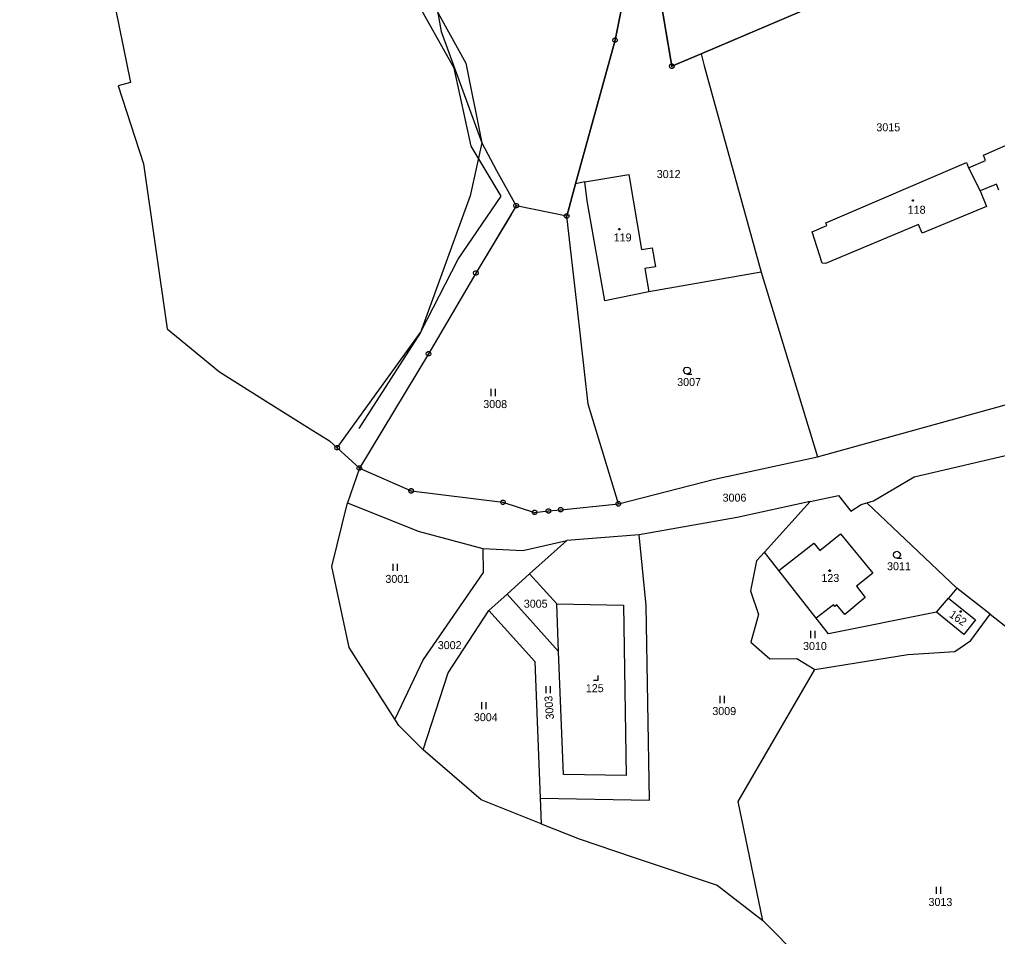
# Model space of a CAD drawing. Extents: x -580551 to -575069, y -1073031 to -1067931.
# Drawn here: x -578557.5 to -578349.8, y -1072489.2 to -1072294.4 of the extents above; entities that cross this region are included whole.
import ezdxf

# ---------------------------------------------------------------- set-up
doc = ezdxf.new("R2010")
doc.units = 0
for name, color, linetype in [('Druh pozemku', 7, 'Continuous'), ('Geodetické body', 7, 'Continuous'), ('Hranice krajů', 7, 'Continuous'), ('Hranice okresů', 7, 'Continuous'), ('Hranice z rastru', 7, 'Continuous'), ('Katastrální hranice', 7, 'Continuous'), ('Parcela', 7, 'Continuous'), ('Parcelní číslo', 7, 'Continuous'), ('Parcelní číslo_stavba', 7, 'Continuous')]:
    doc.layers.add(name, color=color, linetype=linetype)

msp = doc.modelspace()

# ---------------------------------------------------------------- linework, layer by layer
at = {"layer": 'Druh pozemku'}
for p, q in [((-578457.42, -1072372.9), (-578457.42, -1072374.4)), ((-578456.42, -1072374.4), (-578456.42, -1072372.9)), ((-578478.21, -1072410.03), (-578478.21, -1072411.53)), ((-578477.21, -1072411.53), (-578477.21, -1072410.03)), ((-578389.51, -1072424.29), (-578389.51, -1072425.79)), ((-578388.51, -1072425.79), (-578388.51, -1072424.29)), ((-578445.73, -1072435.98), (-578445.73, -1072437.48)), ((-578444.73, -1072437.48), (-578444.73, -1072435.98)), ((-578459.43, -1072439.4), (-578459.43, -1072440.9)), ((-578458.43, -1072440.9), (-578458.43, -1072439.4)), ((-578408.78, -1072438.1), (-578408.78, -1072439.6)), ((-578407.78, -1072439.6), (-578407.78, -1072438.1)), ((-578362.86, -1072478.65), (-578362.86, -1072480.15)), ((-578361.86, -1072480.15), (-578361.86, -1072478.65))]:
    msp.add_line(p, q, dxfattribs=at)
for points in [[(-578367.69, -1072332.7), (-578367.6, -1072332.85), (-578367.69, -1072333), (-578367.87, -1072333), (-578367.96, -1072332.85), (-578367.87, -1072332.7)], [(-578430.04, -1072338.8), (-578429.95, -1072338.95), (-578430.04, -1072339.1), (-578430.22, -1072339.1), (-578430.31, -1072338.95), (-578430.22, -1072338.8)], [(-578385.38, -1072411.34), (-578385.29, -1072411.49), (-578385.38, -1072411.64), (-578385.56, -1072411.64), (-578385.65, -1072411.49), (-578385.56, -1072411.34)], [(-578357.53, -1072420), (-578357.44, -1072420.15), (-578357.53, -1072420.3), (-578357.71, -1072420.3), (-578357.8, -1072420.15), (-578357.71, -1072420)]]:
    msp.add_lwpolyline(points, close=True, dxfattribs=at)
for points in [[(-578415.74, -1072369.72), (-578416.12, -1072369.62), (-578416.39, -1072369.35), (-578416.49, -1072368.98), (-578416.39, -1072368.61), (-578416.12, -1072368.34), (-578415.75, -1072368.24), (-578415.38, -1072368.34), (-578415.11, -1072368.61), (-578415.01, -1072368.99), (-578415.11, -1072369.37), (-578415.38, -1072369.64), (-578415.76, -1072369.74), (-578414.76, -1072369.74)], [(-578371.17, -1072408.84), (-578371.55, -1072408.74), (-578371.82, -1072408.47), (-578371.92, -1072408.1), (-578371.82, -1072407.73), (-578371.55, -1072407.46), (-578371.18, -1072407.36), (-578370.81, -1072407.46), (-578370.54, -1072407.73), (-578370.44, -1072408.11), (-578370.54, -1072408.49), (-578370.81, -1072408.76), (-578371.19, -1072408.86), (-578370.19, -1072408.86)], [(-578435.64, -1072434.74), (-578434.64, -1072434.74), (-578434.64, -1072433.74)]]:
    msp.add_lwpolyline(points, dxfattribs=at)
at = {"layer": 'Geodetické body'}
for p, q in [((-578431.15, -1072298.81), (-578430.91, -1072298.81)), ((-578419.1, -1072304.35), (-578418.86, -1072304.35)), ((-578452.14, -1072333.97), (-578451.9, -1072333.97)), ((-578441.43, -1072336.17), (-578441.19, -1072336.17)), ((-578460.71, -1072348.28), (-578460.47, -1072348.28)), ((-578470.77, -1072365.42), (-578470.53, -1072365.42)), ((-578490.18, -1072385.39), (-578489.94, -1072385.39)), ((-578485.46, -1072389.7), (-578485.22, -1072389.7)), ((-578474.46, -1072394.54), (-578474.22, -1072394.54)), ((-578454.97, -1072396.96), (-578454.73, -1072396.96)), ((-578430.45, -1072397.3), (-578430.21, -1072397.3)), ((-578448.24, -1072399.11), (-578448, -1072399.11)), ((-578445.28, -1072398.81), (-578445.04, -1072398.81)), ((-578442.69, -1072398.54), (-578442.45, -1072398.54))]:
    msp.add_line(p, q, dxfattribs=at)
for points in [[(-578430.88, -1072298.33), (-578430.63, -1072298.51), (-578430.53, -1072298.8), (-578430.63, -1072299.09), (-578430.88, -1072299.27), (-578431.19, -1072299.27), (-578431.44, -1072299.09), (-578431.54, -1072298.8), (-578431.44, -1072298.51), (-578431.19, -1072298.33)], [(-578418.83, -1072303.87), (-578418.58, -1072304.05), (-578418.48, -1072304.34), (-578418.58, -1072304.63), (-578418.83, -1072304.81), (-578419.14, -1072304.81), (-578419.39, -1072304.63), (-578419.49, -1072304.34), (-578419.39, -1072304.05), (-578419.14, -1072303.87)], [(-578451.87, -1072333.49), (-578451.62, -1072333.67), (-578451.52, -1072333.96), (-578451.62, -1072334.25), (-578451.87, -1072334.43), (-578452.18, -1072334.43), (-578452.43, -1072334.25), (-578452.53, -1072333.96), (-578452.43, -1072333.67), (-578452.18, -1072333.49)], [(-578441.16, -1072335.69), (-578440.91, -1072335.87), (-578440.81, -1072336.16), (-578440.91, -1072336.45), (-578441.16, -1072336.63), (-578441.47, -1072336.63), (-578441.72, -1072336.45), (-578441.82, -1072336.16), (-578441.72, -1072335.87), (-578441.47, -1072335.69)], [(-578460.44, -1072347.8), (-578460.19, -1072347.98), (-578460.09, -1072348.27), (-578460.19, -1072348.56), (-578460.44, -1072348.74), (-578460.75, -1072348.74), (-578461, -1072348.56), (-578461.1, -1072348.27), (-578461, -1072347.98), (-578460.75, -1072347.8)], [(-578470.5, -1072364.94), (-578470.25, -1072365.12), (-578470.15, -1072365.41), (-578470.25, -1072365.7), (-578470.5, -1072365.88), (-578470.81, -1072365.88), (-578471.06, -1072365.7), (-578471.16, -1072365.41), (-578471.06, -1072365.12), (-578470.81, -1072364.94)], [(-578489.91, -1072384.91), (-578489.66, -1072385.09), (-578489.56, -1072385.38), (-578489.66, -1072385.67), (-578489.91, -1072385.85), (-578490.22, -1072385.85), (-578490.47, -1072385.67), (-578490.57, -1072385.38), (-578490.47, -1072385.09), (-578490.22, -1072384.91)], [(-578485.19, -1072389.22), (-578484.94, -1072389.4), (-578484.84, -1072389.69), (-578484.94, -1072389.98), (-578485.19, -1072390.16), (-578485.5, -1072390.16), (-578485.75, -1072389.98), (-578485.85, -1072389.69), (-578485.75, -1072389.4), (-578485.5, -1072389.22)], [(-578474.19, -1072394.06), (-578473.94, -1072394.24), (-578473.84, -1072394.53), (-578473.94, -1072394.82), (-578474.19, -1072395), (-578474.5, -1072395), (-578474.75, -1072394.82), (-578474.85, -1072394.53), (-578474.75, -1072394.24), (-578474.5, -1072394.06)], [(-578454.7, -1072396.48), (-578454.45, -1072396.66), (-578454.35, -1072396.95), (-578454.45, -1072397.24), (-578454.7, -1072397.42), (-578455.01, -1072397.42), (-578455.26, -1072397.24), (-578455.36, -1072396.95), (-578455.26, -1072396.66), (-578455.01, -1072396.48)], [(-578442.42, -1072398.06), (-578442.17, -1072398.24), (-578442.07, -1072398.53), (-578442.17, -1072398.82), (-578442.42, -1072399), (-578442.73, -1072399), (-578442.98, -1072398.82), (-578443.08, -1072398.53), (-578442.98, -1072398.24), (-578442.73, -1072398.06)], [(-578430.18, -1072396.82), (-578429.93, -1072397), (-578429.83, -1072397.29), (-578429.93, -1072397.58), (-578430.18, -1072397.76), (-578430.49, -1072397.76), (-578430.74, -1072397.58), (-578430.84, -1072397.29), (-578430.74, -1072397), (-578430.49, -1072396.82)], [(-578447.97, -1072398.63), (-578447.72, -1072398.81), (-578447.62, -1072399.1), (-578447.72, -1072399.39), (-578447.97, -1072399.57), (-578448.28, -1072399.57), (-578448.53, -1072399.39), (-578448.63, -1072399.1), (-578448.53, -1072398.81), (-578448.28, -1072398.63)], [(-578445.01, -1072398.33), (-578444.76, -1072398.51), (-578444.66, -1072398.8), (-578444.76, -1072399.09), (-578445.01, -1072399.27), (-578445.32, -1072399.27), (-578445.57, -1072399.09), (-578445.67, -1072398.8), (-578445.57, -1072398.51), (-578445.32, -1072398.33)]]:
    msp.add_lwpolyline(points, close=True, dxfattribs=at)
at = {"layer": 'Hranice krajů'}
for points in [[(-578557.51, -1072174.96), (-578550.37, -1072227.11), (-578533.93, -1072307.84)], [(-578533.93, -1072307.84), (-578536.54, -1072308.49), (-578531.21, -1072325.07), (-578526.18, -1072360.15)], [(-578526.18, -1072360.15), (-578515.06, -1072369.29), (-578505.29, -1072375.399), (-578495.79, -1072381.34), (-578491.69, -1072383.899), (-578490.06, -1072385.39)]]:
    msp.add_lwpolyline(points, dxfattribs=at)
at = {"layer": 'Hranice okresů'}
msp.add_line((-578485.34, -1072389.7), (-578490.06, -1072385.39), dxfattribs=at)
for points in [[(-578328.77, -1072330.86), (-578333.88, -1072306.58), (-578349.6, -1072274.81), (-578373.44, -1072284.96), (-578412.74, -1072301.69), (-578418.98, -1072304.35), (-578421.46, -1072289.64), (-578423.21, -1072279.21), (-578426.43, -1072275.55), (-578429.77, -1072292.43), (-578431.03, -1072298.81), (-578439.43, -1072329.32)], [(-578439.43, -1072329.32), (-578441.31, -1072336.17), (-578452.02, -1072333.97)], [(-578452.02, -1072333.97), (-578460.59, -1072348.28), (-578470.65, -1072365.42), (-578485.34, -1072389.7)]]:
    msp.add_lwpolyline(points, dxfattribs=at)
at = {"layer": 'Hranice z rastru'}
msp.add_lwpolyline([(-578475.845, -1072252.797), (-578472.35, -1072272.45), (-578467.985, -1072296.997), (-578459.31, -1072320.64), (-578461.799, -1072331.901), (-578472.33, -1072360.9), (-578485.476, -1072381.291)], dxfattribs=at)
at = {"layer": 'Katastrální hranice'}
for p, q in [((-578465.22, -1072304.75), (-578474.67, -1072287.88)), ((-578461.63, -1072321.3), (-578465.22, -1072304.75)), ((-578455.26, -1072331.98), (-578461.63, -1072321.3)), ((-578464.35, -1072345.31), (-578455.26, -1072331.98)), ((-578472.33, -1072360.9), (-578464.35, -1072345.31)), ((-578490.06, -1072385.39), (-578472.33, -1072360.9)), ((-578490.06, -1072385.39), (-578485.34, -1072389.7)), ((-578485.34, -1072389.7), (-578487.84, -1072397.05)), ((-578491.2, -1072410.63), (-578487.84, -1072397.05)), ((-578487.48, -1072427.82), (-578491.2, -1072410.63)), ((-578477.79, -1072443.04), (-578487.48, -1072427.82)), ((-578476.96, -1072444.35), (-578477.79, -1072443.04)), ((-578473.88, -1072447.42), (-578476.96, -1072444.35)), ((-578471.76, -1072449.54), (-578473.88, -1072447.42)), ((-578459.47, -1072460.12), (-578471.76, -1072449.54)), ((-578446.7, -1072465.24), (-578459.47, -1072460.12)), ((-578446.7, -1072465.24), (-578438.65, -1072468.46)), ((-578438.65, -1072468.46), (-578427.21, -1072472.3)), ((-578427.21, -1072472.3), (-578409.37, -1072478.3)), ((-578409.37, -1072478.3), (-578399.64, -1072485.79)), ((-578367.74, -1072517.76), (-578399.64, -1072485.79))]:
    msp.add_line(p, q, dxfattribs=at)
at = {"layer": 'Parcela'}
for p, q in [((-578412.74, -1072301.69), (-578373.44, -1072284.96)), ((-578472.06, -1072286.72), (-578462.73, -1072303.73)), ((-578421.46, -1072289.64), (-578418.98, -1072304.35)), ((-578431.03, -1072298.81), (-578429.77, -1072292.43)), ((-578439.43, -1072329.32), (-578431.03, -1072298.81)), ((-578418.98, -1072304.35), (-578412.74, -1072301.69)), ((-578412.74, -1072301.69), (-578412.13, -1072304.26)), ((-578462.73, -1072303.73), (-578459.31, -1072320.64)), ((-578412.13, -1072304.26), (-578400.02, -1072348.12)), ((-578352.79, -1072323.26), (-578339.13, -1072317.2)), ((-578459.31, -1072320.64), (-578456.25, -1072326.48)), ((-578352.37, -1072324.4), (-578352.79, -1072323.26)), ((-578386.28, -1072337.63), (-578356.41, -1072324.81)), ((-578356.41, -1072324.81), (-578355.99, -1072325.95)), ((-578355.99, -1072325.95), (-578352.37, -1072324.4)), ((-578456.25, -1072326.48), (-578452.02, -1072333.97)), ((-578437.44, -1072328.9), (-578428.12, -1072327.37)), ((-578428.12, -1072327.37), (-578425.42, -1072343.29)), ((-578355.99, -1072325.95), (-578353.52, -1072330.83)), ((-578441.31, -1072336.17), (-578439.43, -1072329.32)), ((-578437.44, -1072328.9), (-578439.43, -1072329.32)), ((-578436.93, -1072332.95), (-578437.44, -1072328.9)), ((-578350.05, -1072329.39), (-578353.52, -1072330.83)), ((-578349.5, -1072330.66), (-578350.05, -1072329.39)), ((-578353.52, -1072330.83), (-578352.15, -1072334.13)), ((-578433.24, -1072354.17), (-578436.93, -1072332.95)), ((-578452.02, -1072333.97), (-578453.13, -1072335.82)), ((-578441.31, -1072336.17), (-578452.02, -1072333.97)), ((-578352.15, -1072334.13), (-578365.81, -1072339.81)), ((-578453.13, -1072335.82), (-578460.59, -1072348.28)), ((-578439.11, -1072355.34), (-578441.31, -1072336.17)), ((-578386.04, -1072338.19), (-578386.28, -1072337.63)), ((-578389.18, -1072339.54), (-578386.04, -1072338.19)), ((-578387.08, -1072346.16), (-578389.18, -1072339.54)), ((-578366.56, -1072337.99), (-578386.37, -1072346.23)), ((-578365.81, -1072339.81), (-578366.56, -1072337.99)), ((-578425.42, -1072343.29), (-578423.16, -1072342.94)), ((-578423.16, -1072342.94), (-578422.48, -1072346.96)), ((-578386.37, -1072346.23), (-578387.08, -1072346.16)), ((-578422.48, -1072346.96), (-578424.71, -1072347.34)), ((-578424.71, -1072347.34), (-578423.84, -1072352.29)), ((-578400.02, -1072348.12), (-578423.84, -1072352.29)), ((-578400.02, -1072348.12), (-578388.04, -1072387.29)), ((-578460.59, -1072348.28), (-578470.65, -1072365.42)), ((-578423.84, -1072352.29), (-578433.24, -1072354.17)), ((-578436.72, -1072376.14), (-578439.11, -1072355.34)), ((-578470.65, -1072365.42), (-578485.34, -1072389.7)), ((-578388.04, -1072387.29), (-578319.16, -1072368.22)), ((-578430.33, -1072397.3), (-578436.72, -1072376.14)), ((-578367.5, -1072391.52), (-578310.43, -1072378.3)), ((-578409.94, -1072392.02), (-578388.04, -1072387.29)), ((-578485.34, -1072389.7), (-578474.34, -1072394.54)), ((-578376.14, -1072396.68), (-578367.5, -1072391.52)), ((-578430.33, -1072397.3), (-578409.94, -1072392.02)), ((-578474.34, -1072394.54), (-578454.85, -1072396.96)), ((-578389.62, -1072396.82), (-578383.56, -1072395.5)), ((-578383.56, -1072395.5), (-578380.96, -1072398.82)), ((-578487.84, -1072397.05), (-578472.85, -1072403.11)), ((-578454.85, -1072396.96), (-578448.12, -1072399.11)), ((-578442.57, -1072398.54), (-578430.33, -1072397.3)), ((-578389.62, -1072396.82), (-578405.09, -1072400.17)), ((-578399.31, -1072407.56), (-578389.62, -1072396.82)), ((-578380.96, -1072398.82), (-578378.78, -1072397.4)), ((-578378.78, -1072397.4), (-578377.58, -1072397.07)), ((-578377.58, -1072397.07), (-578376.14, -1072396.68)), ((-578377.58, -1072397.07), (-578358.42, -1072415.17)), ((-578448.12, -1072399.11), (-578445.16, -1072398.81)), ((-578445.16, -1072398.81), (-578442.57, -1072398.54)), ((-578405.09, -1072400.17), (-578425.93, -1072403.89)), ((-578472.85, -1072403.11), (-578459.1, -1072406.8)), ((-578425.93, -1072403.89), (-578441.27, -1072405.05)), ((-578424.4, -1072418.89), (-578425.93, -1072403.89)), ((-578387.58, -1072407.17), (-578383.19, -1072403.64)), ((-578383.19, -1072403.64), (-578376.29, -1072411.98)), ((-578450.6, -1072407.19), (-578441.27, -1072405.05)), ((-578441.27, -1072405.05), (-578449.18, -1072412.17)), ((-578396.28, -1072411.42), (-578388.83, -1072405.62)), ((-578388.83, -1072405.62), (-578387.58, -1072407.17)), ((-578459.1, -1072406.8), (-578459.07, -1072411.88)), ((-578459.1, -1072406.8), (-578450.6, -1072407.19)), ((-578399.31, -1072407.56), (-578400.98, -1072409.42)), ((-578396.28, -1072411.42), (-578399.31, -1072407.56)), ((-578400.98, -1072409.42), (-578402.24, -1072415.8)), ((-578459.07, -1072411.88), (-578471.79, -1072430.34)), ((-578449.18, -1072412.17), (-578453.97, -1072416.49)), ((-578443.43, -1072418.55), (-578449.18, -1072412.17)), ((-578388.33, -1072421.55), (-578396.28, -1072411.42)), ((-578376.29, -1072411.98), (-578379.74, -1072414.77)), ((-578453.97, -1072416.49), (-578457.83, -1072419.96)), ((-578453.97, -1072416.49), (-578443.02, -1072428.65)), ((-578402.24, -1072415.8), (-578400.57, -1072420.8)), ((-578379.74, -1072414.77), (-578377.9, -1072417.18)), ((-578358.42, -1072415.17), (-578360.22, -1072417.29)), ((-578351.38, -1072420.7), (-578358.42, -1072415.17)), ((-578443.02, -1072428.65), (-578443.43, -1072418.55)), ((-578443.43, -1072418.55), (-578429.25, -1072418.84)), ((-578429.25, -1072418.84), (-578428.69, -1072455.01)), ((-578384.63, -1072418.74), (-578388.33, -1072421.55)), ((-578384.35, -1072419.06), (-578384.63, -1072418.74)), ((-578383.91, -1072418.75), (-578384.35, -1072419.06)), ((-578382.26, -1072420.78), (-578383.91, -1072418.75)), ((-578377.9, -1072417.18), (-578382.26, -1072420.78)), ((-578362.79, -1072420.33), (-578360.22, -1072417.29)), ((-578360.22, -1072417.29), (-578354.47, -1072421.93)), ((-578466.5, -1072433.16), (-578457.83, -1072419.96)), ((-578457.83, -1072419.96), (-578448.09, -1072430.78)), ((-578423.75, -1072460.24), (-578424.4, -1072418.89)), ((-578400.57, -1072420.8), (-578402.22, -1072426.7)), ((-578362.79, -1072420.33), (-578385.7, -1072424.9)), ((-578356.97, -1072425.03), (-578362.79, -1072420.33)), ((-578355.51, -1072426.3), (-578351.38, -1072420.7)), ((-578351.38, -1072420.7), (-578345.04, -1072425.7)), ((-578385.7, -1072424.9), (-578388.33, -1072421.55)), ((-578354.47, -1072421.93), (-578356.97, -1072425.03)), ((-578402.22, -1072426.7), (-578398.15, -1072430.2)), ((-578358.84, -1072428.62), (-578355.51, -1072426.3)), ((-578441.97, -1072454.74), (-578443.02, -1072428.65)), ((-578388.63, -1072432.44), (-578368.83, -1072429.26)), ((-578368.83, -1072429.26), (-578358.84, -1072428.62)), ((-578471.79, -1072430.34), (-578477.79, -1072443.04)), ((-578448.09, -1072430.78), (-578446.92, -1072459.77)), ((-578398.15, -1072430.2), (-578392.45, -1072430.14)), ((-578392.45, -1072430.14), (-578388.63, -1072432.44)), ((-578471.76, -1072449.54), (-578466.5, -1072433.16)), ((-578404.92, -1072460.48), (-578388.63, -1072432.44)), ((-578428.69, -1072455.01), (-578441.97, -1072454.74)), ((-578446.92, -1072459.77), (-578423.75, -1072460.24)), ((-578446.92, -1072459.77), (-578446.7, -1072465.24)), ((-578399.64, -1072485.79), (-578404.92, -1072460.48))]:
    msp.add_line(p, q, dxfattribs=at)

# ---------------------------------------------------------------- texts
at = {"layer": 'Parcelní číslo'}
for s, p in [('3015', (-578375.537, -1072318.17)), ('3012', (-578422.181, -1072328.1)), ('3007', (-578417.841, -1072372.27)), ('3008', (-578459.024, -1072376.95)), ('3006', (-578408.196, -1072396.82)), ('3011', (-578373.269, -1072411.39)), ('3001', (-578479.809, -1072414.08)), ('3005', (-578450.418, -1072419.35)), ('3002', (-578468.691, -1072428.15)), ('3010', (-578391.109, -1072428.34)), ('3004', (-578461.026, -1072443.45)), ('3009', (-578410.376, -1072442.15)), ('3013', (-578364.463, -1072482.7))]:
    msp.add_text(s, height=1.7, dxfattribs=at).set_placement(p)
msp.add_text('3003', height=1.7, rotation=94.30885, dxfattribs=at).set_placement((-578444.002, -1072443.042))
at = {"layer": 'Parcelní číslo_stavba'}
for s, p in [('118', (-578368.878, -1072335.68)), ('119', (-578431.32, -1072341.56)), ('123', (-578387.209, -1072413.88)), ('125', (-578437.244, -1072437.29))]:
    msp.add_text(s, height=1.7, dxfattribs=at).set_placement(p)
msp.add_text('162', height=1.7, rotation=325.32544, dxfattribs=at).set_placement((-578360.232, -1072421.176))

doc.saveas('drawing.dxf')
